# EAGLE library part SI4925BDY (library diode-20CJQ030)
Vishay Siliconix Si4925BDY Dual P-Channel 30-V (D-S) MOSFET FEATURES: TrenchFET Power MOSFET Advanced High Cell Density Process APPLICATIONS: Load Switches ? Notebook PCs ? Desktop PCs ? Game Stations Please send any comments to: messi@users.sourceforge.net
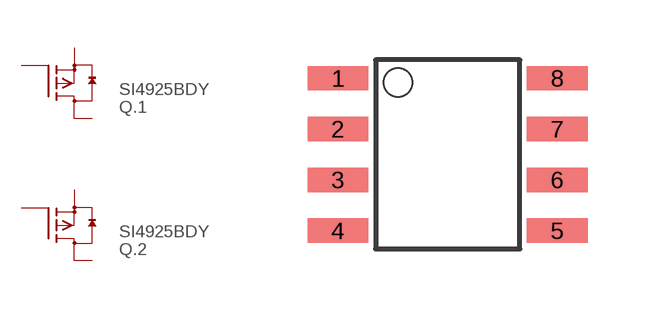
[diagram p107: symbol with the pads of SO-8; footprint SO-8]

Designator prefix Q; gates .1=IGFET-4-P-CH .2=IGFET-4-P-CH

## SI4925BDY  [SO-8]
1  .1:S  pas
2  .1:G  pas
3  .2:S  pas
4  .2:G  pas
5  .2:D  pas
6  .2:D  pas
7  .1:D  pas
8  .1:D  pas

## Footprint SO-8 (pad centres in mm)
small outline
smd 1.524 x 0.61: 1 -2.743,1.27; 2 -2.743,0; 3 -2.743,-1.27; 4 -2.743,-2.54; 5 2.743,-2.54; 6 2.743,-1.27; 7 2.743,0; 8 2.743,1.27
